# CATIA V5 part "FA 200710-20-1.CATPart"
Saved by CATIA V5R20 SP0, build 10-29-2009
Part number: FA 200710-20-1
Revision: ANY
Definition: UNKNOWN
Nomenclature: FA 200710-20-1
Source: Unknown
Bounding box of the stored display mesh (mm): x -10 to 10, y 0.13 to 20.13, z -10 to 10
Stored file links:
  C:\Users\Utente\Desktop\IO LAVORO\3D X SITO CF\CUMSA\3D files FA\FA 200710-20\FA 200710-20-1.CATPart

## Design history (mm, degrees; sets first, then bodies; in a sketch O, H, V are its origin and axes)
Body1 "Cortar-Extruir4" (main body)
  Solid1: solid without history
